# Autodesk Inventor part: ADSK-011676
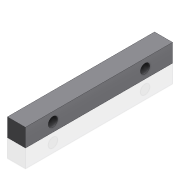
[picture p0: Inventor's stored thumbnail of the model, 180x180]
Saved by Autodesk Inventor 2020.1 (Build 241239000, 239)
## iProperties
Created: 2000-02
Part Number: ADSK-011676
Material: Pearson HRS
Document SubType Name: Modeling
Description: PLT-02,FC,AX,05,040,005,33,IDLER_BRKT_GUIDE
Designer: glanglot
Density: 7.83 g/cm^3
Appearance: Métal - Acier
Mass: 118.094 g
Surface Area: 57.9402 cm^2
Volume: 15.0822 cm^3
Control State: 0
Checked Out: False
Master: False
Shininess: 0.0
Length Units: 11269
Angle Units: 11279
Time Units: 11290
Mass Units: 11283
Length Display Precision: 3
Angle Display Precision: 2
Compacted: True
Cutlength: 4.0
Material Desc: FLAT,CRS,0.500X00.500
Material_Number: A084161
DocNumber: ADSK-011676.ipt
Folder: 01 - Themengebiete\Simplification\04-Packaging machine\
VDS_Category: 3D Komponenten
Dimensions: 12,5x12,5x102 mm
Mass: 0,118 kg
Density: 0.0
Volumn: 0.0
Area: 0.0
PropertySet Name: Model Information
Author: glanglot
Revision Number: -
Title: PLT-02,FC,AX,05,040,005,33,IDLER_BRKT_GUIDE
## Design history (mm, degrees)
node "Solide1"
  node "Extrusion1" dims "d2" = 102, "d3" = 0
  node "Hole1" dims "d6" = 6.6, "d7" = 9.525, "d8" = 6.35, "d9" = 60 deg, "d10" = 19.05, "d11" = 118 deg, "d12" = 6
sketch "Sketch1"
  geometry: L1 (0, 0)-(12.5, 0); L2 (12.5, 0)-(12.5, 12.5); L3 (12.5, 12.5)-(0, 12.5); L4 (0, 12.5)-(0, 0)
  constraints: 8 end point, 2 parallel, 1 horizontal, 1 perpendicular
  dimensions: "d0" = 12.5 distance between parallel lines of L4 L2; "d1" = 12.5 distance between parallel lines of L3 L1 (= d0)
sketch "Sketch2"
  geometry: L1 (0, 12.5)-(0, 0) reference; L2 (19.25, 6.25)-(82.75, 6.25); L3 (0, 12.5)-(102, 12.5) reference; 3 further points
  constraints: 3 midpoint, 2 end point, 1 horizontal, 1 horizontal alignment, 1 vertical alignment
  dimensions: "d13" = 63.5 distance of L2.end L2.start
node "Corps solides"
node "Corps surfaciques"
